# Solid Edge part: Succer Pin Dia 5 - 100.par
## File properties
Author: Dan
Template: metric part.par
Last saved by: Dan
Revision: 6
Application: Solid Edge
Density: 7833.000 kg/m^3
Accuracy: 0.990
Material: Steel
Face Style: Steel
Fill Style: ANSI32(Steel)
Virtual Style: Machined steel
Coef. of Thermal Exp: 1.3e-05
Thermal Conductivity: 32.0
Specific Heat: 481.0
Modulus of Elasticity: 199947953000.0
Poisson's Ratio: 0.29
Yield Stress: 262000766.0
Ultimate Stress: 358527364.0
Elongation: 0.0
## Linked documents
Dia 5 - 100.par
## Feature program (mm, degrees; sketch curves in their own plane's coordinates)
part copy "CopiedPart_1"
sketch for "unnamed RevolvedCutout 1" plane through (0, 0, 0) normal (0, 0, 1) x-axis (1, 0, 0)
revolve "unnamed RevolvedCutout 1" cut finite 360 deg about sketch line (34.5125, 0) -> (31.2142, 0)
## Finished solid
Body 1: solid body, 7 faces, 6 edges, 0 vertices.
  Faces by surface: plane 3, cylinder 2, torus 2
  Edges by curve: circle 6
Bounding box of the edges (mm; curved faces can reach further): 34.513 x 10.000 x 10.000, from (0, -5, -5) to (34.5125, 5, 5).
Cylindrical faces by radius (mm): R2.5 x1, R5 x1
Toroidal faces (ring radius, tube radius in mm): R0.95 r0.8697 x1, R2.5 r0.8503 x1
Planar faces by outward normal: +x 2, -x 1
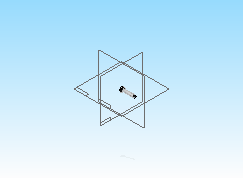
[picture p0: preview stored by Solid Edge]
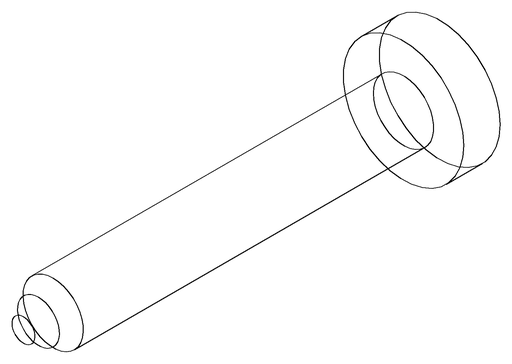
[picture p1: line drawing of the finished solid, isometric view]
